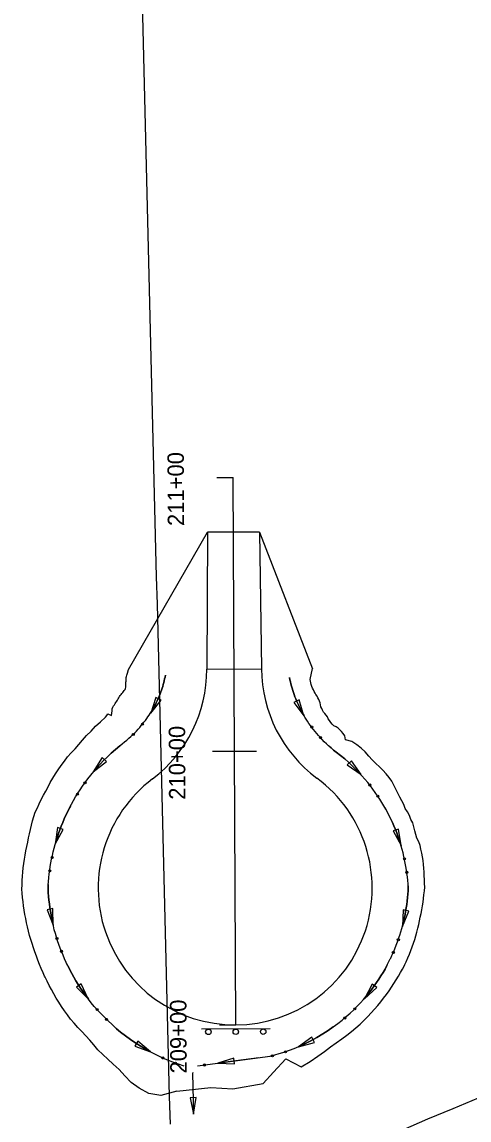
# Model space of a CAD drawing. Extents: x 1611108 to 1749517, y 619561 to 797725.
# Drawn here: x 1722849.6 to 1723012.8, y 768807.5 to 769208.7 of the extents above; entities that cross this region are included whole.
import ezdxf

# ---------------------------------------------------------------- set-up
doc = ezdxf.new("R2010")
doc.units = 0
for name, color, linetype in [('R_Ditch', 7, 'Continuous'), ('R_Guardrail', 7, 'Continuous'), ('R_Horz Alg', 7, 'Continuous'), ('R_Horz Alg Stationing_Side Road', 7, 'Continuous'), ('R_Proposed Const Limits', 7, 'Continuous'), ('R_Proposed Road', 7, 'Continuous'), ('R_Proposed Road_101173', 7, 'Continuous'), ('R_Special Ditch', 7, 'Continuous')]:
    doc.layers.add(name, color=color, linetype=linetype)

msp = doc.modelspace()

# ---------------------------------------------------------------- linework, layer by layer
at = {"layer": 'R_Ditch'}
for p, q in [((1722898.49, 768961.92), (1722896.64, 768956.11)), ((1722896.64, 768956.11), (1722900.37, 768960.93)), ((1722900.37, 768960.93), (1722898.49, 768961.92)), ((1722878.88, 768939.9), (1722875.64, 768934.74)), ((1722880.45, 768938.48), (1722878.88, 768939.9)), ((1722875.64, 768934.74), (1722880.45, 768938.48)), ((1722862.6, 768914.38), (1722861.71, 768908.35)), ((1722861.71, 768908.35), (1722864.61, 768913.71)), ((1722864.61, 768913.71), (1722862.6, 768914.38)), ((1722860.88, 768884.76), (1722858.8, 768884.36)), ((1722858.8, 768884.36), (1722860.97, 768878.67)), ((1722860.97, 768878.67), (1722860.88, 768884.76)), ((1722871.19, 768857.23), (1722869.47, 768856)), ((1722869.47, 768856), (1722873.82, 768851.74)), ((1722873.82, 768851.74), (1722871.19, 768857.23)), ((1722891.87, 768836.32), (1722890.8, 768834.49)), ((1722896.51, 768832.38), (1722891.87, 768836.32)), ((1722890.8, 768834.49), (1722896.51, 768832.38))]:
    msp.add_line(p, q, dxfattribs=at)
for points in [[(1722893.46, 769215.95), (1722893.7, 769205.95), (1722893.94, 769195.95), (1722894.18, 769185.96), (1722894.43, 769175.96), (1722894.67, 769165.96), (1722894.92, 769155.96), (1722895.17, 769145.97), (1722895.42, 769135.97), (1722895.67, 769125.97), (1722895.91, 769115.98), (1722896.16, 769105.98), (1722896.41, 769095.98), (1722896.66, 769085.98), (1722896.91, 769075.99), (1722897.16, 769065.99), (1722897.41, 769055.99), (1722897.66, 769046), (1722897.91, 769036), (1722898.16, 769026), (1722898.41, 769016), (1722898.66, 769006.01), (1722898.91, 768996.01), (1722899.16, 768986.01), (1722899.41, 768976.02), (1722899.66, 768966.02), (1722899.91, 768956.02), (1722900.16, 768946.03), (1722900.41, 768936.03), (1722900.65, 768926.03), (1722900.91, 768916.03), (1722901.15, 768906.04), (1722901.4, 768896.04), (1722901.65, 768886.04), (1722901.9, 768876.05), (1722902.15, 768866.05), (1722902.4, 768856.05), (1722902.65, 768846.06), (1722902.9, 768836.06), (1722903.15, 768826.06), (1722903.4, 768816.06), (1722903.65, 768806.07)], [(1722893.46, 769215.95), (1722893.7, 769205.95), (1722893.94, 769195.95), (1722894.18, 769185.96), (1722894.43, 769175.96), (1722894.67, 769165.96), (1722894.92, 769155.96), (1722895.17, 769145.97), (1722895.42, 769135.97), (1722895.67, 769125.97), (1722895.91, 769115.98), (1722896.16, 769105.98), (1722896.41, 769095.98), (1722896.66, 769085.98), (1722896.91, 769075.99), (1722897.16, 769065.99), (1722897.41, 769055.99), (1722897.66, 769046), (1722897.91, 769036), (1722898.16, 769026), (1722898.41, 769016), (1722898.66, 769006.01), (1722898.91, 768996.01), (1722899.16, 768986.01), (1722899.41, 768976.02), (1722899.66, 768966.02), (1722899.91, 768956.02), (1722900.16, 768946.03), (1722900.41, 768936.03), (1722900.65, 768926.03), (1722900.91, 768916.03), (1722901.15, 768906.04), (1722901.4, 768896.04), (1722901.65, 768886.04), (1722901.9, 768876.05), (1722902.15, 768866.05), (1722902.4, 768856.05), (1722902.65, 768846.06), (1722902.9, 768836.06), (1722903.15, 768826.06), (1722903.4, 768816.06), (1722903.65, 768806.07)], [(1722908.78, 768827.17), (1722904.67, 768828.62), (1722901.27, 768830.05), (1722898.33, 768831.45), (1722895.72, 768832.84), (1722893.36, 768834.22), (1722891.2, 768835.59), (1722889.21, 768836.95), (1722887.36, 768838.31), (1722885.63, 768839.66), (1722884.01, 768841.01), (1722882.49, 768842.36), (1722881.06, 768843.7), (1722879.7, 768845.04), (1722878.41, 768846.38), (1722877.19, 768847.71), (1722876.03, 768849.05), (1722874.93, 768850.38), (1722873.88, 768851.71), (1722872.88, 768853.04), (1722871.93, 768854.38), (1722871.03, 768855.71), (1722870.16, 768857.04), (1722869.34, 768858.37), (1722868.56, 768859.7), (1722867.82, 768861.03), (1722867.11, 768862.36), (1722866.43, 768863.69), (1722866.28, 768864.01), (1722865.8, 768865.03), (1722865.19, 768866.36), (1722864.62, 768867.69), (1722864.07, 768869.03), (1722863.56, 768870.36), (1722863.08, 768871.7), (1722862.63, 768873.04), (1722862.2, 768874.38), (1722861.81, 768875.72), (1722861.44, 768877.06), (1722861.1, 768878.41), (1722860.79, 768879.75), (1722860.5, 768881.1), (1722860.24, 768882.45), (1722860.01, 768883.8), (1722859.81, 768885.15), (1722859.63, 768886.51), (1722859.47, 768887.87), (1722859.34, 768889.23), (1722859.24, 768890.59), (1722859.17, 768891.95), (1722859.24, 768893.32), (1722859.33, 768894.68), (1722859.46, 768896.04), (1722859.6, 768897.4), (1722859.78, 768898.75), (1722859.98, 768900.11), (1722860.21, 768901.46), (1722860.46, 768902.81), (1722860.74, 768904.15), (1722861.05, 768905.5), (1722861.38, 768906.84), (1722861.74, 768908.19), (1722862.13, 768909.53), (1722862.55, 768910.87), (1722863, 768912.21), (1722863.47, 768913.54), (1722863.98, 768914.88), (1722864.51, 768916.21), (1722865.08, 768917.55), (1722865.68, 768918.88), (1722866.31, 768920.21), (1722866.97, 768921.55), (1722867.67, 768922.88), (1722868.41, 768924.21), (1722869.19, 768925.54), (1722870, 768926.87), (1722870.85, 768928.2), (1722871.75, 768929.53), (1722872.69, 768930.86), (1722873.68, 768932.2), (1722874.72, 768933.53), (1722875.81, 768934.86), (1722876.96, 768936.2), (1722878.17, 768937.54), (1722879.44, 768938.88), (1722880.79, 768940.22), (1722882.21, 768941.57), (1722883.72, 768942.91), (1722885.32, 768944.27), (1722887.03, 768945.62), (1722887.87, 768946.3), (1722888.66, 768946.97), (1722889.41, 768947.64), (1722890.11, 768948.3), (1722890.77, 768948.96), (1722891.41, 768949.62), (1722892.01, 768950.28), (1722892.58, 768950.94), (1722893.12, 768951.59), (1722893.64, 768952.25), (1722894.16, 768952.88), (1722894.66, 768953.52), (1722895.14, 768954.16), (1722895.6, 768954.8), (1722896.04, 768955.44), (1722896.46, 768956.08), (1722896.86, 768956.73), (1722897.25, 768957.37), (1722897.62, 768958.02), (1722897.98, 768958.67), (1722898.32, 768959.32), (1722898.65, 768959.97), (1722898.96, 768960.62), (1722899.26, 768961.28), (1722899.55, 768961.94), (1722899.82, 768962.6), (1722900.08, 768963.26), (1722900.33, 768963.93), (1722900.56, 768964.6), (1722900.78, 768965.27), (1722900.99, 768965.95), (1722901.18, 768966.62), (1722901.36, 768967.3), (1722901.53, 768967.99), (1722901.69, 768968.67), (1722901.83, 768969.36), (1722901.97, 768970.05)], [(1722901.97, 768970.05), (1722901.83, 768969.36), (1722901.69, 768968.67), (1722901.53, 768967.99), (1722901.36, 768967.3), (1722901.18, 768966.62), (1722900.99, 768965.95), (1722900.78, 768965.27), (1722900.56, 768964.6), (1722900.33, 768963.93), (1722900.08, 768963.26), (1722899.82, 768962.6), (1722899.55, 768961.94), (1722899.26, 768961.28), (1722898.96, 768960.62), (1722898.65, 768959.97), (1722898.32, 768959.32), (1722897.98, 768958.67), (1722897.62, 768958.02), (1722897.25, 768957.37), (1722896.86, 768956.73), (1722896.52, 768956.18)], [(1722886.42, 768945.14), (1722885.32, 768944.27), (1722883.72, 768942.91), (1722882.21, 768941.57), (1722880.79, 768940.22), (1722879.44, 768938.88), (1722878.17, 768937.54), (1722876.96, 768936.2), (1722875.81, 768934.86), (1722875.68, 768934.71)], [(1722886.45, 768945.16), (1722886.42, 768945.14)], [(1722867.33, 768922.23), (1722866.97, 768921.55), (1722866.31, 768920.21), (1722865.68, 768918.88), (1722865.08, 768917.55), (1722864.51, 768916.21), (1722863.98, 768914.88), (1722863.47, 768913.54), (1722863, 768912.21), (1722862.55, 768910.87), (1722862.13, 768909.53), (1722861.78, 768908.33)], [(1722867.35, 768922.26), (1722867.33, 768922.23)], [(1722859.25, 768893.53), (1722859.24, 768893.32), (1722859.17, 768891.95), (1722859.24, 768890.59), (1722859.34, 768889.23), (1722859.47, 768887.87), (1722859.63, 768886.51), (1722859.81, 768885.15), (1722860.01, 768883.8), (1722860.24, 768882.45), (1722860.5, 768881.1), (1722860.79, 768879.75), (1722861.04, 768878.68)], [(1722859.25, 768893.57), (1722859.25, 768893.53)], [(1722866.02, 768864.56), (1722866.03, 768864.53)], [(1722866.03, 768864.53), (1722866.28, 768864.01), (1722866.43, 768863.69), (1722867.11, 768862.36), (1722867.82, 768861.03), (1722868.56, 768859.7), (1722869.34, 768858.37), (1722870.16, 768857.04), (1722871.03, 768855.71), (1722871.93, 768854.38), (1722872.88, 768853.04), (1722873.85, 768851.76)], [(1722884.15, 768840.9), (1722884.18, 768840.87)], [(1722884.18, 768840.87), (1722885.63, 768839.66), (1722887.36, 768838.31), (1722889.21, 768836.95), (1722891.2, 768835.59), (1722893.36, 768834.22), (1722895.72, 768832.84), (1722896.53, 768832.41)]]:
    msp.add_lwpolyline(points, dxfattribs=at)
for centre in [(1722893.59, 768952.12), (1722890.25, 768948.39), (1722872.64, 768930.73), (1722869.86, 768926.57), (1722860.63, 768903.46), (1722859.79, 768898.52), (1722862.4, 768873.87), (1722864.07, 768869.15), (1722877.06, 768847.92), (1722880.51, 768844.29), (1722901.02, 768830.2), (1722905.66, 768828.31)]:
    msp.add_circle(centre, 0.375, dxfattribs=at)
at = {"layer": 'R_Guardrail'}
msp.add_line((1722940.18, 768840.83), (1722915.18, 768840.71), dxfattribs=at)
for centre in [(1722917.66, 768839.72), (1722927.66, 768839.77), (1722937.66, 768839.82)]:
    msp.add_circle(centre, 1, dxfattribs=at)
at = {"layer": 'R_Horz Alg'}
msp.add_line((1722927.67, 768842.27), (1722926.74, 769042.27), dxfattribs=at)
at = {"layer": 'R_Horz Alg Stationing_Side Road'}
for p, q in [((1722920.74, 769042.24), (1722926.74, 769042.27)), ((1722921.67, 768842.24), (1722927.67, 768842.27))]:
    msp.add_line(p, q, dxfattribs=at)
msp.add_lwpolyline([(1722919.2, 768942.23), (1722935.2, 768942.31)], dxfattribs=at)
at = {"layer": 'R_Proposed Const Limits'}
msp.add_line((1722936.33, 769022.31), (1722955.6, 768972.4), dxfattribs=at)
msp.add_line((1722936.33, 769022.31), (1722955.6, 768972.4), dxfattribs=at)
for points in [[(1722906.17, 768818.07), (1722900.33, 768816.48), (1722895.87, 768817.2), (1722892.45, 768819.16), (1722889.53, 768821.26), (1722887.19, 768823.72), (1722885.06, 768826), (1722882.94, 768827.89), (1722880.99, 768829.74), (1722879.11, 768831.46), (1722877.34, 768833.14), (1722875.84, 768834.97), (1722874.41, 768836.74), (1722872.91, 768838.33), (1722871.5, 768839.91), (1722870.05, 768841.38), (1722868.68, 768842.86), (1722867.4, 768844.38), (1722866.23, 768845.92), (1722865.13, 768847.47), (1722864.08, 768849.01), (1722863.08, 768850.55), (1722862.13, 768852.09), (1722861.22, 768853.63), (1722860.37, 768855.17), (1722859.55, 768856.7), (1722858.78, 768858.23), (1722858.05, 768859.76), (1722857.88, 768860.12), (1722857.35, 768861.29), (1722856.69, 768862.82), (1722856.06, 768864.34), (1722855.46, 768865.87), (1722854.89, 768867.39), (1722854.35, 768868.91), (1722853.84, 768870.43), (1722853.34, 768871.95), (1722852.87, 768873.47), (1722852.43, 768874.99), (1722852.02, 768876.51), (1722851.65, 768878.04), (1722851.3, 768879.57), (1722850.99, 768881.1), (1722850.71, 768882.63), (1722850.45, 768884.17), (1722850.23, 768885.71), (1722850.04, 768887.26), (1722849.87, 768888.8), (1722849.74, 768890.35), (1722849.64, 768891.91), (1722849.68, 768893.46), (1722849.74, 768895.02), (1722849.84, 768896.57), (1722849.97, 768898.12), (1722850.12, 768899.68), (1722850.31, 768901.23), (1722850.53, 768902.78), (1722850.79, 768904.33), (1722851.07, 768905.88), (1722851.39, 768907.42), (1722851.76, 768908.97), (1722851.99, 768910.55), (1722852.34, 768912.11), (1722852.74, 768913.68), (1722853.11, 768915.27), (1722853.52, 768916.85), (1722853.96, 768918.45), (1722854.48, 768920.03), (1722855.29, 768921.52), (1722855.96, 768923.07), (1722856.67, 768924.62), (1722857.45, 768926.16), (1722858.35, 768927.66), (1722859.19, 768929.2), (1722859.96, 768930.81), (1722860.88, 768932.37), (1722861.84, 768933.93), (1722862.85, 768935.49), (1722863.92, 768937.05), (1722865.11, 768938.57), (1722866.22, 768940.18), (1722867.59, 768941.64), (1722869.06, 768943.08), (1722870.39, 768944.68), (1722871.78, 768946.32), (1722873.23, 768947.99), (1722874.87, 768949.56), (1722876.43, 768951.36), (1722878.24, 768953.01), (1722880.13, 768954.74), (1722880.56, 768955.33), (1722880.96, 768955.89), (1722882.34, 768955.34), (1722882.43, 768956.19), (1722882.51, 768956.99), (1722882.59, 768957.73), (1722882.74, 768958.35), (1722883.07, 768958.79), (1722883.37, 768959.23), (1722883.65, 768959.67), (1722883.94, 768960.09), (1722884.22, 768960.51), (1722884.49, 768960.92), (1722884.75, 768961.34), (1722884.97, 768961.76), (1722885.19, 768962.18), (1722885.45, 768962.57), (1722885.77, 768962.93), (1722886.08, 768963.29), (1722886.39, 768963.66), (1722886.69, 768964.03), (1722886.97, 768964.42), (1722887.3, 768964.78), (1722887.47, 768965.2), (1722887.5, 768965.67), (1722887.53, 768966.12), (1722887.55, 768966.58), (1722887.57, 768967.02), (1722887.59, 768967.46), (1722887.6, 768967.9), (1722887.61, 768968.33), (1722887.61, 768968.76), (1722887.7, 768969.17), (1722887.82, 768969.58), (1722887.93, 768969.99), (1722888.05, 768970.4), (1722888.18, 768970.82), (1722888.5, 768972.09), (1722917.33, 769022.22)], [(1722906.17, 768818.07), (1722918.5, 768819.37), (1722926.55, 768818.95), (1722937.67, 768820.91), (1722941.42, 768824.99), (1722945.96, 768829.84), (1722951.5, 768826.93), (1722954.77, 768828.92), (1722957.56, 768830.8), (1722960, 768832.6), (1722962.19, 768834.32), (1722964.31, 768835.76), (1722966.3, 768837.14), (1722968.14, 768838.52), (1722969.86, 768839.89), (1722971.48, 768841.25), (1722973, 768842.6), (1722974.44, 768843.96), (1722975.8, 768845.3), (1722977.08, 768846.65), (1722978.31, 768848), (1722979.46, 768849.34), (1722980.57, 768850.69), (1722981.61, 768852.03), (1722982.61, 768853.37), (1722983.56, 768854.71), (1722984.47, 768856.05), (1722985.36, 768857.38), (1722986.21, 768858.7), (1722987.02, 768860.03), (1722987.79, 768861.36), (1722988.53, 768862.69), (1722989.23, 768864.02), (1722989.39, 768864.33), (1722989.87, 768865.37), (1722990.46, 768866.72), (1722991.02, 768868.07), (1722991.54, 768869.43), (1722992.04, 768870.78), (1722992.5, 768872.14), (1722992.94, 768873.5), (1722993.34, 768874.85), (1722993.72, 768876.21), (1722994.07, 768877.57), (1722994.39, 768878.93), (1722994.68, 768880.29), (1722994.97, 768881.65), (1722995.26, 768883), (1722995.52, 768884.36), (1722995.76, 768885.72), (1722995.98, 768887.09), (1722996.17, 768888.46), (1722996.33, 768889.83), (1722996.47, 768891.21), (1722996.58, 768892.59), (1722996.55, 768893.97), (1722996.49, 768895.36), (1722996.41, 768896.74), (1722996.34, 768898.12), (1722996.26, 768899.51), (1722996.16, 768900.9), (1722996.03, 768902.29), (1722995.79, 768903.68), (1722995.53, 768905.06), (1722995.23, 768906.44), (1722994.91, 768907.82), (1722994.41, 768909.16), (1722993.73, 768910.45), (1722993.38, 768911.84), (1722993, 768913.22), (1722992.59, 768914.61), (1722992.25, 768916.04), (1722991.52, 768917.34), (1722991.03, 768918.74), (1722990.36, 768920.08), (1722989.46, 768921.32), (1722988.93, 768922.75), (1722988.3, 768924.16), (1722987.51, 768925.5), (1722986.81, 768926.92), (1722986.06, 768928.33), (1722985.34, 768929.8), (1722984.58, 768931.28), (1722983.6, 768932.65), (1722982.48, 768933.96), (1722981.33, 768935.27), (1722980.12, 768936.57), (1722978.75, 768937.78), (1722977.41, 768939.05), (1722976.15, 768940.47), (1722974.91, 768941.98), (1722973.43, 768943.35), (1722971.78, 768944.62), (1722969.99, 768945.82), (1722967.69, 768946.47), (1722967.49, 768947.91), (1722966.89, 768948.74), (1722966.28, 768949.47), (1722965.65, 768950.12), (1722964.99, 768950.71), (1722964.27, 768951.21), (1722963.4, 768951.56), (1722962.82, 768952.16), (1722962.3, 768952.79), (1722961.8, 768953.42), (1722961.42, 768954.11), (1722961.09, 768954.82), (1722960.6, 768955.4), (1722960.13, 768955.98), (1722959.67, 768956.56), (1722959.32, 768957.2), (1722959.02, 768957.85), (1722958.71, 768958.49), (1722958.55, 768959.19), (1722958.41, 768959.88), (1722958.23, 768960.54), (1722957.94, 768961.15), (1722957.64, 768961.75), (1722957.33, 768962.35), (1722956.92, 768962.91), (1722956.58, 768963.5), (1722956.24, 768964.1), (1722955.95, 768964.7), (1722955.69, 768965.32), (1722955.44, 768965.94), (1722955.21, 768966.57), (1722955.05, 768967.21), (1722954.91, 768967.85), (1722954.78, 768968.49), (1722955.6, 768972.41)], [(1723016.05, 768815.56), (1723006.83, 768811.67), (1722997.62, 768807.79), (1722988.43, 768803.85)]]:
    msp.add_lwpolyline(points, dxfattribs=at)
at = {"layer": 'R_Proposed Road'}
for p, q in [((1722917.33, 769022.22), (1722917.06, 768972.22)), ((1722936.33, 769022.31), (1722917.33, 769022.22)), ((1722936.33, 769022.31), (1722937.06, 768972.32)), ((1722917.06, 768972.22), (1722937.06, 768972.32)), ((1722921.67, 768842.24), (1722927.67, 768842.27))]:
    msp.add_line(p, q, dxfattribs=at)
for centre, start, end in [((1722867.06, 768971.99), 307.1366, 0.2667), ((1722867.06, 768971.99), 307.1366, 0.2667), ((1722987.06, 768972.55), 180.2667, 233.3968), ((1722987.06, 768972.55), 180.2667, 233.3968), ((1722987.06, 768972.55), 180.2667, 233.3968), ((1722987.06, 768972.55), 180.2667, 233.3968), ((1722987.06, 768972.55), 180.2667, 233.3968), ((1722927.44, 768892.27), 127.1366, 270.2667), ((1722927.44, 768892.27), 127.1366, 270.2667), ((1722927.44, 768892.27), 270.2667, 53.3968), ((1722927.44, 768892.27), 270.2667, 53.3968), ((1722927.44, 768892.27), 270.2667, 53.3968), ((1722927.44, 768892.27), 270.2667, 53.3968), ((1722927.44, 768892.27), 270.2667, 53.3968)]:
    msp.add_arc(centre, 50, start, end, dxfattribs=at)
at = {"layer": 'R_Proposed Road_101173'}
for centre, start, end in [((1722867.06, 768971.99), 307.1366, 0.2667), ((1722987.06, 768972.55), 180.2667, 233.3968), ((1722927.44, 768892.27), 127.1366, 270.2667), ((1722927.44, 768892.27), 270.2667, 53.3968)]:
    msp.add_arc(centre, 50, start, end, dxfattribs=at)
at = {"layer": 'R_Special Ditch'}
for p, q in [((1722950.73, 768961), (1722948.84, 768960.06)), ((1722948.84, 768960.06), (1722952.46, 768955.16)), ((1722952.46, 768955.16), (1722950.73, 768961)), ((1722969.82, 768938.73), (1722968.34, 768937.22)), ((1722968.34, 768937.22), (1722973.37, 768933.78)), ((1722973.37, 768933.78), (1722969.82, 768938.73)), ((1722987.05, 768913.81), (1722985.05, 768913.12)), ((1722985.05, 768913.12), (1722988.01, 768907.8)), ((1722988.01, 768907.8), (1722987.05, 768913.81)), ((1722988.74, 768884.27), (1722988.45, 768878.18)), ((1722988.45, 768878.18), (1722990.81, 768883.8)), ((1722990.81, 768883.8), (1722988.74, 768884.27)), ((1722977.39, 768857.2), (1722974.56, 768851.81)), ((1722974.56, 768851.81), (1722979.07, 768855.91)), ((1722979.07, 768855.91), (1722977.39, 768857.2)), ((1722955.4, 768837.8), (1722950.48, 768834.21)), ((1722950.48, 768834.21), (1722956.34, 768835.9)), ((1722956.34, 768835.9), (1722955.4, 768837.8)), ((1722926.97, 768830.14), (1722921.16, 768828.31)), ((1722921.16, 768828.31), (1722927.24, 768828.04)), ((1722927.24, 768828.04), (1722926.97, 768830.14)), ((1722913.14, 768815.71), (1722911.02, 768815.65)), ((1722911.02, 768815.65), (1722912.25, 768809.68)), ((1722912.25, 768809.68), (1722913.14, 768815.71))]:
    msp.add_line(p, q, dxfattribs=at)
for points in [[(1722913.71, 768827.32), (1722940.21, 768830.82), (1722945.24, 768832.28), (1722949.01, 768833.67), (1722952.14, 768835.02), (1722954.84, 768836.35), (1722957.24, 768837.66), (1722959.41, 768838.95), (1722961.39, 768840.24), (1722963.21, 768841.52), (1722964.91, 768842.79), (1722966.49, 768844.05), (1722967.97, 768845.31), (1722969.37, 768846.57), (1722970.68, 768847.82), (1722971.92, 768849.07), (1722973.1, 768850.31), (1722974.22, 768851.56), (1722975.28, 768852.8), (1722976.28, 768854.04), (1722977.24, 768855.28), (1722978.15, 768856.51), (1722979.02, 768857.75), (1722979.85, 768858.99), (1722980.63, 768860.22), (1722981.38, 768861.46), (1722982.1, 768862.69), (1722982.77, 768863.93), (1722983.42, 768865.16), (1722984.03, 768866.4), (1722984.17, 768866.69), (1722984.61, 768867.63), (1722985.16, 768868.87), (1722985.69, 768870.1), (1722986.18, 768871.34), (1722986.64, 768872.58), (1722987.08, 768873.82), (1722987.49, 768875.06), (1722987.87, 768876.3), (1722988.23, 768877.54), (1722988.56, 768878.78), (1722988.87, 768880.03), (1722989.15, 768881.27), (1722989.41, 768882.52), (1722989.64, 768883.77), (1722989.85, 768885.02), (1722990.03, 768886.27), (1722990.19, 768887.53), (1722990.32, 768888.78), (1722990.43, 768890.04), (1722990.52, 768891.3), (1722990.59, 768892.56), (1722990.5, 768893.83), (1722990.4, 768895.08), (1722990.27, 768896.34), (1722990.12, 768897.59), (1722989.94, 768898.85), (1722989.74, 768900.1), (1722989.51, 768901.34), (1722989.27, 768902.59), (1722988.99, 768903.83), (1722988.69, 768905.07), (1722988.37, 768906.31), (1722988.02, 768907.55), (1722987.65, 768908.78), (1722987.25, 768910.02), (1722986.82, 768911.25), (1722986.37, 768912.48), (1722985.89, 768913.71), (1722985.38, 768914.94), (1722984.84, 768916.16), (1722984.27, 768917.39), (1722983.68, 768918.62), (1722983.05, 768919.84), (1722982.39, 768921.06), (1722981.69, 768922.29), (1722980.96, 768923.51), (1722980.2, 768924.73), (1722979.4, 768925.95), (1722978.56, 768927.17), (1722977.68, 768928.39), (1722976.75, 768929.62), (1722975.78, 768930.84), (1722974.76, 768932.06), (1722973.69, 768933.28), (1722972.56, 768934.51), (1722971.37, 768935.74), (1722970.12, 768936.96), (1722968.79, 768938.2), (1722967.39, 768939.43), (1722965.89, 768940.67), (1722964.3, 768941.91), (1722963.32, 768942.68), (1722962.41, 768943.44), (1722961.54, 768944.2), (1722960.72, 768944.96), (1722959.95, 768945.72), (1722959.21, 768946.48), (1722958.51, 768947.23), (1722957.85, 768947.98), (1722957.21, 768948.74), (1722956.61, 768949.49), (1722956.01, 768950.22), (1722955.44, 768950.96), (1722954.89, 768951.69), (1722954.36, 768952.43), (1722953.85, 768953.17), (1722953.37, 768953.91), (1722952.9, 768954.65), (1722952.46, 768955.39), (1722952.03, 768956.14), (1722951.62, 768956.88), (1722951.23, 768957.63), (1722950.86, 768958.38), (1722950.5, 768959.14), (1722950.16, 768959.89), (1722949.83, 768960.65), (1722949.52, 768961.41), (1722949.23, 768962.17), (1722948.95, 768962.94), (1722948.69, 768963.71), (1722948.44, 768964.48), (1722948.21, 768965.25), (1722947.99, 768966.03), (1722947.79, 768966.81), (1722947.6, 768967.59), (1722947.42, 768968.38), (1722947.26, 768969.17)], [(1722947.26, 768969.17), (1722947.42, 768968.38), (1722947.6, 768967.59), (1722947.79, 768966.81), (1722947.99, 768966.03), (1722948.21, 768965.25), (1722948.44, 768964.48), (1722948.69, 768963.71), (1722948.95, 768962.94), (1722949.23, 768962.17), (1722949.52, 768961.41), (1722949.83, 768960.65), (1722950.16, 768959.89), (1722950.5, 768959.14), (1722950.86, 768958.38), (1722951.23, 768957.63), (1722951.62, 768956.88), (1722952.03, 768956.14), (1722952.46, 768955.39), (1722952.56, 768955.21)], [(1722962.1, 768943.71), (1722962.13, 768943.69)], [(1722962.13, 768943.69), (1722962.41, 768943.44), (1722963.32, 768942.68), (1722964.3, 768941.91), (1722965.89, 768940.67), (1722967.39, 768939.43), (1722968.79, 768938.2), (1722970.12, 768936.96), (1722971.37, 768935.74), (1722972.56, 768934.51), (1722973.3, 768933.71)], [(1722982.09, 768921.59), (1722982.11, 768921.56)], [(1722982.11, 768921.56), (1722982.39, 768921.06), (1722983.05, 768919.84), (1722983.68, 768918.62), (1722984.27, 768917.39), (1722984.84, 768916.16), (1722985.38, 768914.94), (1722985.89, 768913.71), (1722986.37, 768912.48), (1722986.82, 768911.25), (1722987.25, 768910.02), (1722987.65, 768908.78), (1722987.95, 768907.78)], [(1722990.56, 768893), (1722990.59, 768892.56), (1722990.52, 768891.3), (1722990.43, 768890.04), (1722990.32, 768888.78), (1722990.19, 768887.53), (1722990.03, 768886.27), (1722989.85, 768885.02), (1722989.64, 768883.77), (1722989.41, 768882.52), (1722989.15, 768881.27), (1722988.87, 768880.03), (1722988.56, 768878.78), (1722988.41, 768878.2)], [(1722990.55, 768893.04), (1722990.56, 768893)], [(1722982.93, 768864.22), (1722982.77, 768863.93), (1722982.1, 768862.69), (1722981.38, 768861.46), (1722980.63, 768860.22), (1722979.85, 768858.99), (1722979.02, 768857.75), (1722978.15, 768856.51), (1722977.24, 768855.28), (1722976.28, 768854.04), (1722975.28, 768852.8), (1722974.48, 768851.87)], [(1722982.95, 768864.26), (1722982.93, 768864.22)], [(1722963.45, 768841.7), (1722963.21, 768841.52), (1722961.39, 768840.24), (1722959.41, 768838.95), (1722957.24, 768837.66), (1722954.84, 768836.35), (1722952.14, 768835.02), (1722950.45, 768834.29)], [(1722963.48, 768841.72), (1722963.45, 768841.7)], [(1722936.03, 768830.27), (1722921.16, 768828.31)], [(1722936.07, 768830.28), (1722936.03, 768830.27)], [(1722911.82, 768824.71), (1722911.82, 768824.67)], [(1722911.82, 768824.67), (1722912.25, 768809.68)], [(1722911.98, 768824.83), (1722911.94, 768824.82)]]:
    msp.add_lwpolyline(points, dxfattribs=at)
for centre in [(1722955.39, 768951.08), (1722958.57, 768947.22), (1722976.56, 768929.91), (1722979.51, 768925.85), (1722989.23, 768902.94), (1722990.1, 768898), (1722986.97, 768873.4), (1722985.14, 768868.73), (1722971.09, 768848.18), (1722967.41, 768844.79), (1722940.99, 768831.01), (1722945.79, 768832.45), (1722916.2, 768827.62)]:
    msp.add_circle(centre, 0.375, dxfattribs=at)

# ---------------------------------------------------------------- texts
at = {"layer": 'R_Horz Alg Stationing_Side Road'}
for s, p in [('211+00', (1722908.82, 769024.54)), ('210+00', (1722909.29, 768924.54)), ('209+00', (1722909.75, 768824.54))]:
    msp.add_text(s, height=6, rotation=90.2667, dxfattribs=at).set_placement(p)

doc.saveas('drawing.dxf')
